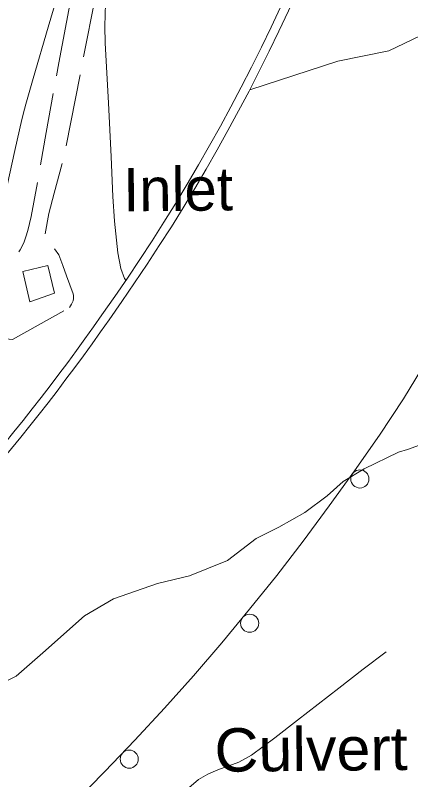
# Model space of a CAD drawing. Extents: x 2361284 to 2366480, y 6976556 to 6985346.
# Drawn here: x 2364887 to 2364930.6, y 6979134.4 to 6979218.9 of the extents above; entities that cross this region are included whole.
import ezdxf

# ---------------------------------------------------------------- set-up
doc = ezdxf.new("R2010")
doc.units = 0
doc.header["$LTSCALE"] = 1.9
for name, color, linetype, lineweight in [('12', 7, 'Continuous', 13), ('13', 7, 'Continuous', 13), ('17', 7, 'Continuous', 13), ('20', 7, 'Continuous', 13), ('3', 7, 'Continuous', 13), ('6', 7, 'Continuous', 13), ('8', 7, 'Continuous', 13)]:
    doc.layers.add(name, color=color, linetype=linetype, lineweight=lineweight)

msp = doc.modelspace()

# ---------------------------------------------------------------- linework, layer by layer
at = {"layer": '12'}
msp.add_lwpolyline([(2364932.844, 6979171.793), (2364930.292, 6979170.869), (2364929.305, 6979170.569), (2364925.513, 6979168.733), (2364923.186, 6979167.341), (2364921.421, 6979165.754), (2364918.957, 6979163.901), (2364916.063, 6979162.273), (2364913.574, 6979161.039), (2364910.407, 6979158.618), (2364906.184, 6979156.908), (2364902.672, 6979156.044), (2364897.798, 6979154.378), (2364894.605, 6979152.477), (2364889.983, 6979148.383), (2364887.068, 6979145.816), (2364882.539, 6979143.583), (2364877.479, 6979142.615), (2364874.263, 6979142.025), (2364866.171, 6979141.218), (2364858.44, 6979142.314)], dxfattribs=at)
at = {"layer": '13'}
for points in [[(2364899.213, 6979189.624), (2364899.156, 6979189.601), (2364899.018, 6979189.761), (2364898.631, 6979190.868), (2364898.29, 6979192.613), (2364897.901, 6979196.112), (2364897.715, 6979198.85), (2364897.564, 6979203.208), (2364897.235, 6979209.206), (2364896.893, 6979215.783), (2364896.841, 6979217.671), (2364896.964, 6979221.443), (2364897.338, 6979225.208), (2364897.699, 6979227.715), (2364898.613, 6979232.72)], [(2364894.255, 6979230.319), (2364893.205, 6979226.471), (2364892.659, 6979224.553), (2364890.596, 6979217.543), (2364888.944, 6979211.885), (2364888.137, 6979209.05), (2364887.983, 6979208.486), (2364887.694, 6979207.354), (2364887.424, 6979206.217), (2364886.905, 6979203.938), (2364885.534, 6979197.704), (2364885.41, 6979197.185), (2364885.142, 6979196.152), (2364884.588, 6979194.09), (2364884.338, 6979193.053), (2364884.167, 6979192.257), (2364883.861, 6979190.658), (2364883.358, 6979187.808), (2364883.122, 6979186.381)], [(2364935.936, 6979218.914), (2364931.688, 6979216.584), (2364928.224, 6979214.921), (2364922.584, 6979213.787), (2364912.853, 6979210.635)]]:
    msp.add_lwpolyline(points, dxfattribs=at)
at = {"layer": '17'}
for points in [[(2364975.707, 6979285.287), (2364974.439, 6979281.924), (2364973.221, 6979278.553), (2364972.14, 6979275.412), (2364971.09, 6979272.252), (2364969.168, 6979266.143), (2364967.236, 6979260.044), (2364964.213, 6979250.956), (2364961.119, 6979241.895), (2364957.7, 6979232.292), (2364954.1, 6979222.757), (2364951.52, 6979216.473), (2364948.678, 6979210.305), (2364944.409, 6979201.833), (2364939.877, 6979193.501), (2364934.959, 6979184.924), (2364929.839, 6979176.464)], [(2364929.839, 6979176.464), (2364927.177, 6979172.449), (2364924.445, 6979168.513), (2364921.641, 6979164.626), (2364918.767, 6979160.749), (2364915.833, 6979156.95), (2364912.828, 6979153.221), (2364909.774, 6979149.502), (2364906.639, 6979145.862), (2364903.453, 6979142.292), (2364900.176, 6979138.751), (2364896.858, 6979135.288), (2364893.501, 6979131.866)]]:
    msp.add_lwpolyline(points, dxfattribs=at)
for centre in [(2364925.025, 6979167.612), (2364912.85, 6979151.671), (2364899.545, 6979136.644)]:
    msp.add_circle(centre, 1, dxfattribs=at)
at = {"layer": '20'}
msp.add_lwpolyline([(2364927.945, 6979148.524), (2364925.403, 6979146.58), (2364922.683, 6979144.485), (2364920.41, 6979142.713), (2364918.145, 6979140.942), (2364915.614, 6979139.008), (2364913.052, 6979137.102), (2364911.649, 6979136.319), (2364909.347, 6979135.467), (2364908.223, 6979134.996), (2364907.188, 6979134.376), (2364905.115, 6979132.577)], dxfattribs=at)
at = {"layer": '3'}
for centre, radius, start, end in [((2364724.701, 6979308.181), 210.974, 324.53485, 345.90885), ((2364724.701, 6979308.181), 211.934, 324.53485, 345.90885), ((2364710.718, 6979315.25), 226.475, 298.99244, 325.12827), ((2364710.718, 6979315.25), 227.435, 298.99244, 325.12827)]:
    msp.add_arc(centre, radius, start, end, dxfattribs=at)
at = {"layer": '6'}
for p, q in [((2364896.043, 6979222.115), (2364894.507, 6979214.26)), ((2364894.126, 6979212.297), (2364892.591, 6979204.442))]:
    msp.add_line(p, q, dxfattribs=at)
for points in [[(2364891.497, 6979212.192), (2364891.753, 6979213.604), (2364892.982, 6979220.056)], [(2364889.74, 6979202.353), (2364890.367, 6979205.901), (2364891.145, 6979210.228)], [(2364892.119, 6979202.496), (2364891.25, 6979199.209), (2364890.652, 6979196.953), (2364890.273, 6979194.719)], [(2364887.332, 6979192.711), (2364887.48, 6979192.943), (2364887.892, 6979193.707), (2364888.136, 6979194.379), (2364888.34, 6979195.061), (2364888.705, 6979196.624), (2364889.02, 6979198.197), (2364889.399, 6979200.381)], [(2364891.289, 6979193.049), (2364891.775, 6979192.393), (2364892.206, 6979191.227), (2364892.627, 6979190.061), (2364892.997, 6979189.065), (2364893.356, 6979188.078), (2364893.398, 6979187.889), (2364893.391, 6979187.559), (2364893.334, 6979187.308), (2364893.167, 6979186.936), (2364892.961, 6979186.564)], [(2364885.152, 6979183.17), (2364886.654, 6979183.034), (2364892.324, 6979186.208)]]:
    msp.add_lwpolyline(points, dxfattribs=at)
at = {"layer": '8'}
msp.add_lwpolyline([(2364890.536, 6979191.212), (2364887.783, 6979190.535), (2364888.564, 6979187.193), (2364891.305, 6979188.169)], close=True, dxfattribs=at)

# ---------------------------------------------------------------- texts
msp.add_text('Inlet', height=4.799, rotation=0.545, dxfattribs=at).set_placement((2364898.891, 6979197.191))
at = {"layer": '8', "width": 1.05}
msp.add_text('Culvert', height=4.799, rotation=0.545, dxfattribs=at).set_placement((2364908.98, 6979135.243))

doc.saveas('drawing.dxf')
